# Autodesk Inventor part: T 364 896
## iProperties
Created: 2006-04
Part Number: T 364 896
Material: 1.0120.01
Description: Halteleiste
Vendor: Autodesk Inc.
Document SubType Name: Modeling
Standard: DIN 174
Designer: I.Baliuc
Standards Organization: DIN
Language: de-DE
Size Designation: 40 x 10 - 0.001
Categories: <MemberInstance Version="R10.0.0"><Categories><Category DisplayName="Profilstahle" InternalName="089c4875-fa83-4c05-b084-43b9cc11f5ed" Mnemonic="GRDR"><Category
Density: 7.84 g/cm^3
Zweck: Vorkontakt HSLT
Abmessung: Fl. 40x10-80
G_L: 80,000 mm
Author: T.Messerschmitt
Revision Number: 364896
Keywords: 380109
Comments: DIN 174
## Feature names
1. Körper [Extrusion]
2. Bohrung_Ø10 [Hole]
3. Bohrung_Ø8.5 [Hole]
4. Bohr_Ø8.5 [Rectangular Pattern]
